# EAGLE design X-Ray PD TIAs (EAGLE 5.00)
MFG: Amp; PN: TPSB476K010R0250
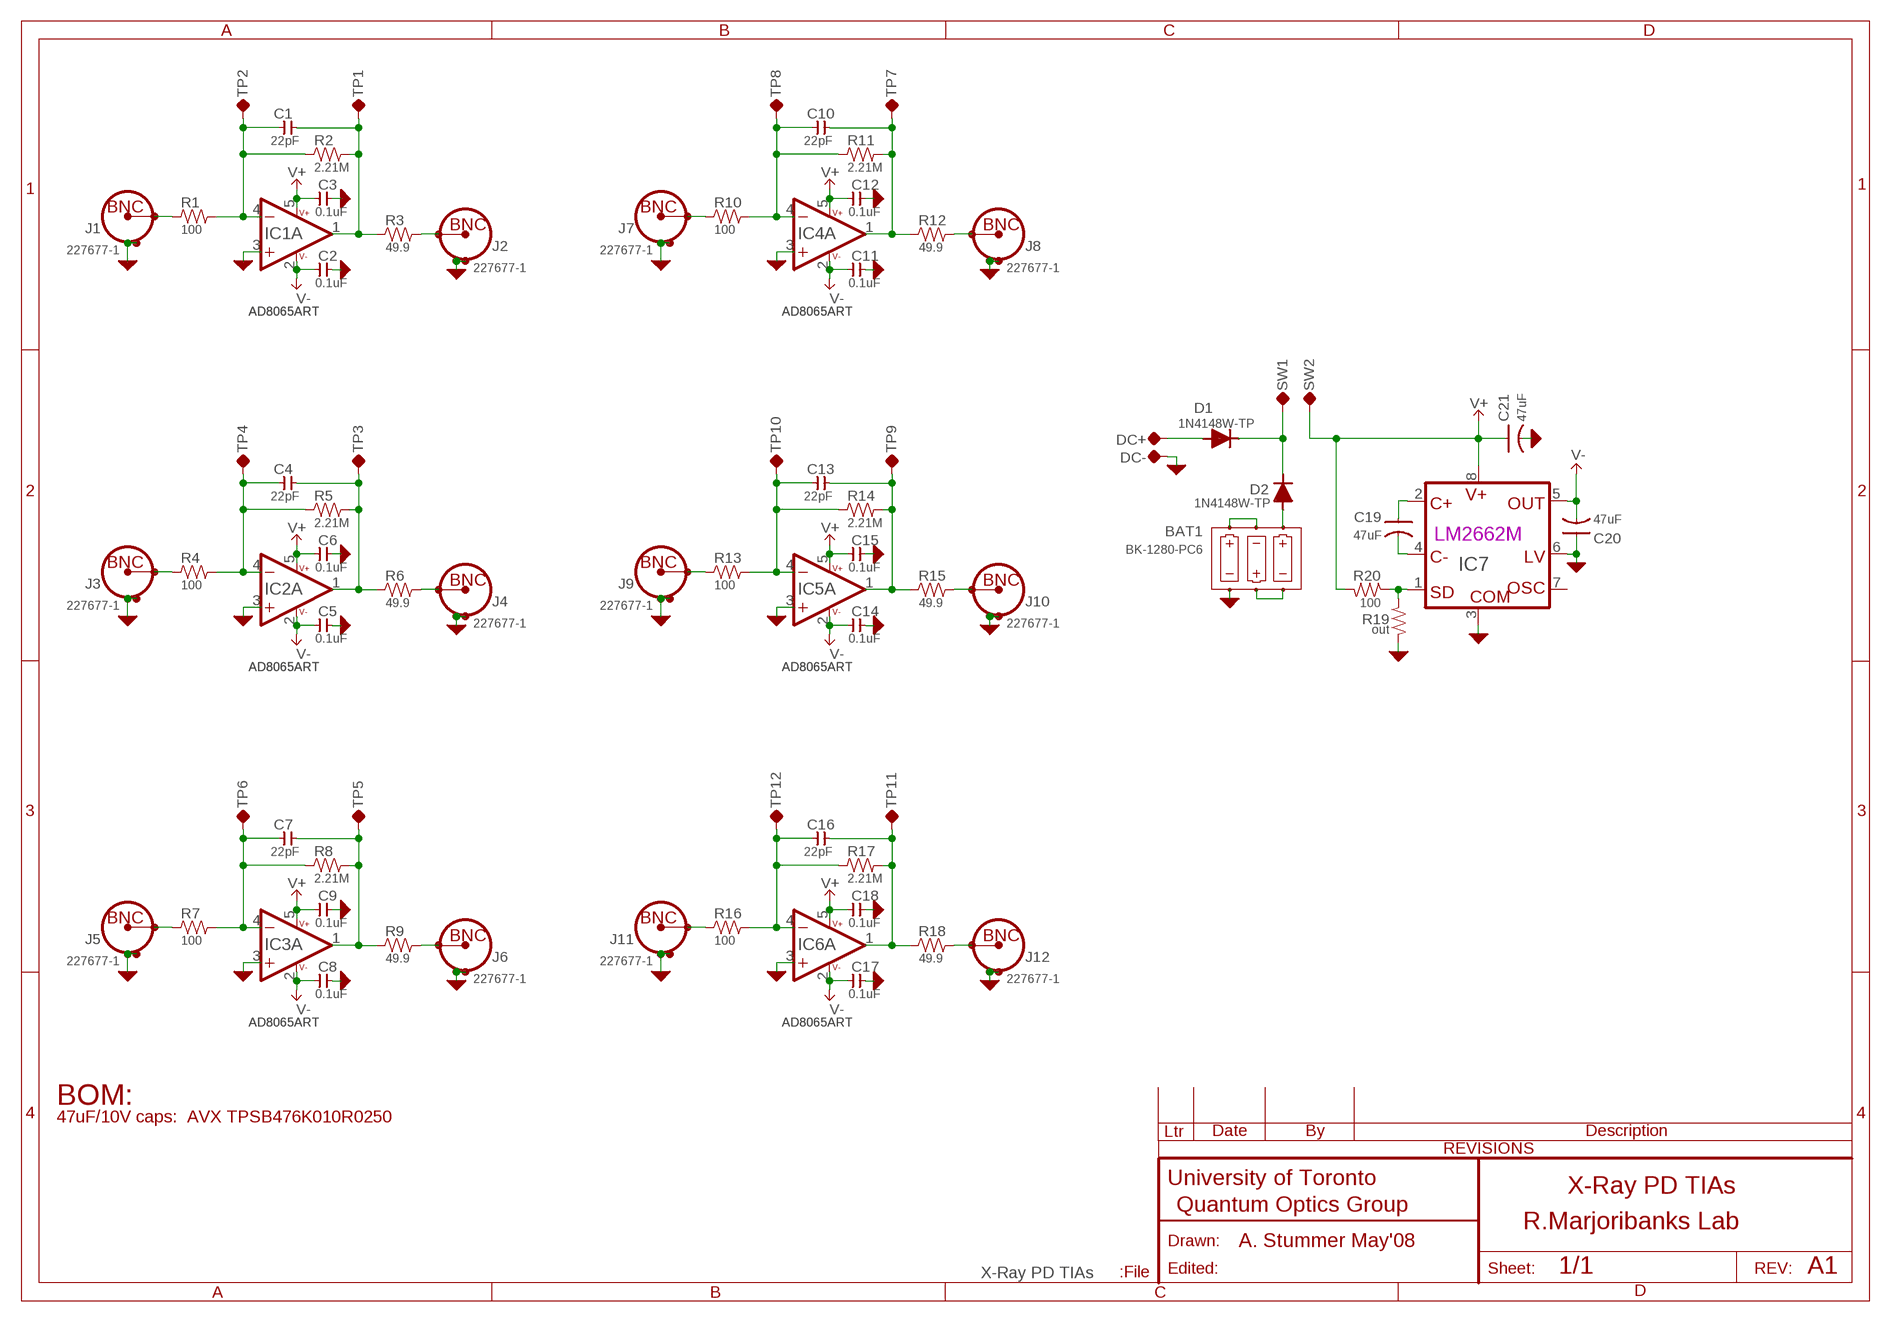
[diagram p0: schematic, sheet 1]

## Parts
BAT1  BK-1280-PC6  BATTERY-CASE-3AA-1  [BATTERY-CASE-3AA-1]
C1  22pF  CAP-H-0805  [2012(0805)]
C2  0.1uF  CAP-H-0805  [2012(0805)]
C3  0.1uF  CAP-H-0805  [2012(0805)]
C4  22pF  CAP-H-0805  [2012(0805)]
C5  0.1uF  CAP-H-0805  [2012(0805)]
C6  0.1uF  CAP-H-0805  [2012(0805)]
C7  22pF  CAP-H-0805  [2012(0805)]
C8  0.1uF  CAP-H-0805  [2012(0805)]
C9  0.1uF  CAP-H-0805  [2012(0805)]
C10  22pF  CAP-H-0805  [2012(0805)]
C11  0.1uF  CAP-H-0805  [2012(0805)]
C12  0.1uF  CAP-H-0805  [2012(0805)]
C13  22pF  CAP-H-0805  [2012(0805)]
C14  0.1uF  CAP-H-0805  [2012(0805)]
C15  0.1uF  CAP-H-0805  [2012(0805)]
C16  22pF  CAP-H-0805  [2012(0805)]
C17  0.1uF  CAP-H-0805  [2012(0805)]
C18  0.1uF  CAP-H-0805  [2012(0805)]
C19  47uF  CAP-POL-EIA-B  [EIA-B(SMB)]
C20  47uF  CAP-POL-EIA-B  [EIA-B(SMB)]
C21  47uF  CAP-POL-EIA-B  [EIA-B(SMB)]
D1  1N4148W-TP  DIODE,GENERIC-SOD123  [SOD123]
D2  1N4148W-TP  DIODE,GENERIC-SOD123  [SOD123]
DC+  TP-0.042"  [TP-0.042]
DC-  TP-0.042"  [TP-0.042]
IC1  AD8065ART  OPAMPSOT23-5  [SOT23-5]
IC2  AD8065ART  OPAMPSOT23-5  [SOT23-5]
IC3  AD8065ART  OPAMPSOT23-5  [SOT23-5]
IC4  AD8065ART  OPAMPSOT23-5  [SOT23-5]
IC5  AD8065ART  OPAMPSOT23-5  [SOT23-5]
IC6  AD8065ART  OPAMPSOT23-5  [SOT23-5]
IC7  LM2662M  LM2663M  [SOIC-8]
J1  227677-1  CONN-BNCTYPE3HORIZ  [CONN-BNC-AMP-TYPE3HORIZ]
J2  227677-1  CONN-BNCTYPE3HORIZ  [CONN-BNC-AMP-TYPE3HORIZ]
J3  227677-1  CONN-BNCTYPE3HORIZ  [CONN-BNC-AMP-TYPE3HORIZ]
J4  227677-1  CONN-BNCTYPE3HORIZ  [CONN-BNC-AMP-TYPE3HORIZ]
J5  227677-1  CONN-BNCTYPE3HORIZ  [CONN-BNC-AMP-TYPE3HORIZ]
J6  227677-1  CONN-BNCTYPE3HORIZ  [CONN-BNC-AMP-TYPE3HORIZ]
J7  227677-1  CONN-BNCTYPE3HORIZ  [CONN-BNC-AMP-TYPE3HORIZ]
J8  227677-1  CONN-BNCTYPE3HORIZ  [CONN-BNC-AMP-TYPE3HORIZ]
J9  227677-1  CONN-BNCTYPE3HORIZ  [CONN-BNC-AMP-TYPE3HORIZ]
J10  227677-1  CONN-BNCTYPE3HORIZ  [CONN-BNC-AMP-TYPE3HORIZ]
J11  227677-1  CONN-BNCTYPE3HORIZ  [CONN-BNC-AMP-TYPE3HORIZ]
J12  227677-1  CONN-BNCTYPE3HORIZ  [CONN-BNC-AMP-TYPE3HORIZ]
R1  100  R-H-0805  [2012(0805)]
R2  2.21M  R-H-0805  [2012(0805)]
R3  49.9  R-H-0805  [2012(0805)]
R4  100  R-H-0805  [2012(0805)]
R5  2.21M  R-H-0805  [2012(0805)]
R6  49.9  R-H-0805  [2012(0805)]
R7  100  R-H-0805  [2012(0805)]
R8  2.21M  R-H-0805  [2012(0805)]
R9  49.9  R-H-0805  [2012(0805)]
R10  100  R-H-0805  [2012(0805)]
R11  2.21M  R-H-0805  [2012(0805)]
R12  49.9  R-H-0805  [2012(0805)]
R13  100  R-H-0805  [2012(0805)]
R14  2.21M  R-H-0805  [2012(0805)]
R15  49.9  R-H-0805  [2012(0805)]
R16  100  R-H-0805  [2012(0805)]
R17  2.21M  R-H-0805  [2012(0805)]
R18  49.9  R-H-0805  [2012(0805)]
R19  out  R-V-0805  [2012(0805)]
R20  100  R-H-0805  [2012(0805)]
SW1  TP-0.042"  [TP-0.042]
SW2  TP-0.042"  [TP-0.042]
TP1  future use  TP-0.042"  [TP-0.042]
TP2  future use  TP-0.042"  [TP-0.042]
TP3  future use  TP-0.042"  [TP-0.042]
TP4  future use  TP-0.042"  [TP-0.042]
TP5  future use  TP-0.042"  [TP-0.042]
TP6  future use  TP-0.042"  [TP-0.042]
TP7  future use  TP-0.042"  [TP-0.042]
TP8  future use  TP-0.042"  [TP-0.042]
TP9  future use  TP-0.042"  [TP-0.042]
TP10  future use  TP-0.042"  [TP-0.042]
TP11  future use  TP-0.042"  [TP-0.042]
TP12  future use  TP-0.042"  [TP-0.042]

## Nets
AGND: BAT1.1- C2.2 C3.2 C5.2 C6.2 C8.2 C9.2 C11.2 C12.2 C14.2 C15.2 C17.2 C18.2 C20.K+(POS) C21.A-(NEG) DC-.TP IC1.3(A:+IN) IC2.3(A:+IN) IC3.3(A:+IN) IC4.3(A:+IN) IC5.3(A:+IN) IC6.3(A:+IN) IC7.3(COM) IC7.6(LV) J1.SHIELD1 J1.SHIELD2 J2.SHIELD1 J2.SHIELD2 J3.SHIELD1 J3.SHIELD2 J4.SHIELD1 J4.SHIELD2 J5.SHIELD1 J5.SHIELD2 J6.SHIELD1 J6.SHIELD2 J7.SHIELD1 J7.SHIELD2 J8.SHIELD1 J8.SHIELD2 J9.SHIELD1 J9.SHIELD2 J10.SHIELD1 J10.SHIELD2 J11.SHIELD1 J11.SHIELD2 J12.SHIELD1 J12.SHIELD2 R19.1
N$1: J1.CONDUCTOR R1.1
N$2: C1.1 IC1.4(A:-IN) R1.2 R2.1 TP2.TP
N$3: C1.2 IC1.1(A:OUT) R2.2 R3.1 TP1.TP
N$4: J2.CONDUCTOR R3.2
N$5: J3.CONDUCTOR R4.1
N$6: C4.1 IC2.4(A:-IN) R4.2 R5.1 TP4.TP
N$7: C4.2 IC2.1(A:OUT) R5.2 R6.1 TP3.TP
N$8: J4.CONDUCTOR R6.2
N$9: J5.CONDUCTOR R7.1
N$10: C7.1 IC3.4(A:-IN) R7.2 R8.1 TP6.TP
N$11: C7.2 IC3.1(A:OUT) R8.2 R9.1 TP5.TP
N$12: J6.CONDUCTOR R9.2
N$13: J7.CONDUCTOR R10.1
N$14: C10.1 IC4.4(A:-IN) R10.2 R11.1 TP8.TP
N$15: C10.2 IC4.1(A:OUT) R11.2 R12.1 TP7.TP
N$16: J8.CONDUCTOR R12.2
N$17: J9.CONDUCTOR R13.1
N$18: C13.1 IC5.4(A:-IN) R13.2 R14.1 TP10.TP
N$19: C13.2 IC5.1(A:OUT) R14.2 R15.1 TP9.TP
N$20: J10.CONDUCTOR R15.2
N$21: J11.CONDUCTOR R16.1
N$22: C16.1 IC6.4(A:-IN) R16.2 R17.1 TP12.TP
N$23: C16.2 IC6.1(A:OUT) R17.2 R18.1 TP11.TP
N$24: J12.CONDUCTOR R18.2
N$25: C19.K+(POS) IC7.2(C+)
N$26: C19.A-(NEG) IC7.4(C-)
N$27: BAT1.1+ BAT1.2-
N$28: BAT1.2+ BAT1.3-
N$29: BAT1.3+ D2.A
N$30: D1.C D2.C SW1.TP
N$31: D1.A DC+.TP
N$32: IC7.1(SD) R19.2 R20.1
V+: C3.1 C6.1 C9.1 C12.1 C15.1 C18.1 C21.K+(POS) IC1.5(B:V+) IC2.5(B:V+) IC3.5(B:V+) IC4.5(B:V+) IC5.5(B:V+) IC6.5(B:V+) IC7.8(V+) R20.2 SW2.TP
V-: C2.1 C5.1 C8.1 C11.1 C14.1 C17.1 C20.A-(NEG) IC1.2(B:V-) IC2.2(B:V-) IC3.2(B:V-) IC4.2(B:V-) IC5.2(B:V-) IC6.2(B:V-) IC7.5(OUT)
Unconnected: IC7.7(OSC)

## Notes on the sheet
- BOM:
- 47uF/10V caps:  AVX TPSB476K010R0250
- X-Ray PD TIAs
- R.Marjoribanks Lab
- A. Stummer May'08
- A1

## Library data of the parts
BAT1 = QuantumOptics:BATTERY-CASE-3AA-1: Battery holder, 3 AA, Memory Protection Devices Inc, BK-1280-PC6
C1-C18 = QuantumOptics:CAP-H-: Cap, SMT and Through-hole, 0402 and up.
C19-C21 = QuantumOptics:CAP-POL-: Capacitor, Polarized, SMT 0805 and up, probably tantalum.
D1 D2 = QuantumOptics:DIODE,GENERIC: Diode, Generic, plain old vanilla diodes.
DC+ DC- SW1 SW2 TP1-TP12 = QuantumOptics:TP: Testpoint, test point on schematic, on PCB either SMT pad, small hole or loop style TP.
IC1-IC6 = QuantumOptics:OPAMP: Op Amp, generic, pick the right package. e.g. AD8605: SOT-23-5, RRIO, 10MHz, Ib = 1pA, Vio < 65uV, 2.7-5.5V.
IC7 = QuantumOptics:LM2663: LM2663, switched cap DC-DC converter. Inverter, doubler, supply splitter.
J1-J12 = QuantumOptics:CONN-BNC: BNC PCB, horizontal, Amp 227677-1, nut 1-329631-2, shoulder washer 330620. The two shield connections allow the assembly on either side of the board. http://catalog.tycoelectronics.com/TE/bin/TE.Connect?C=1&PN=227677-1&M=STARTSWITH&LG=1&I=13&button.x=0&button.y=0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
R1-R18 R20 = QuantumOptics:R-H-*: Resistor, SMT & Through-Hole, horizontal symbol
R19 = QuantumOptics:R-V-*: Resistor, SMT & Through-Hole, vertical symbol

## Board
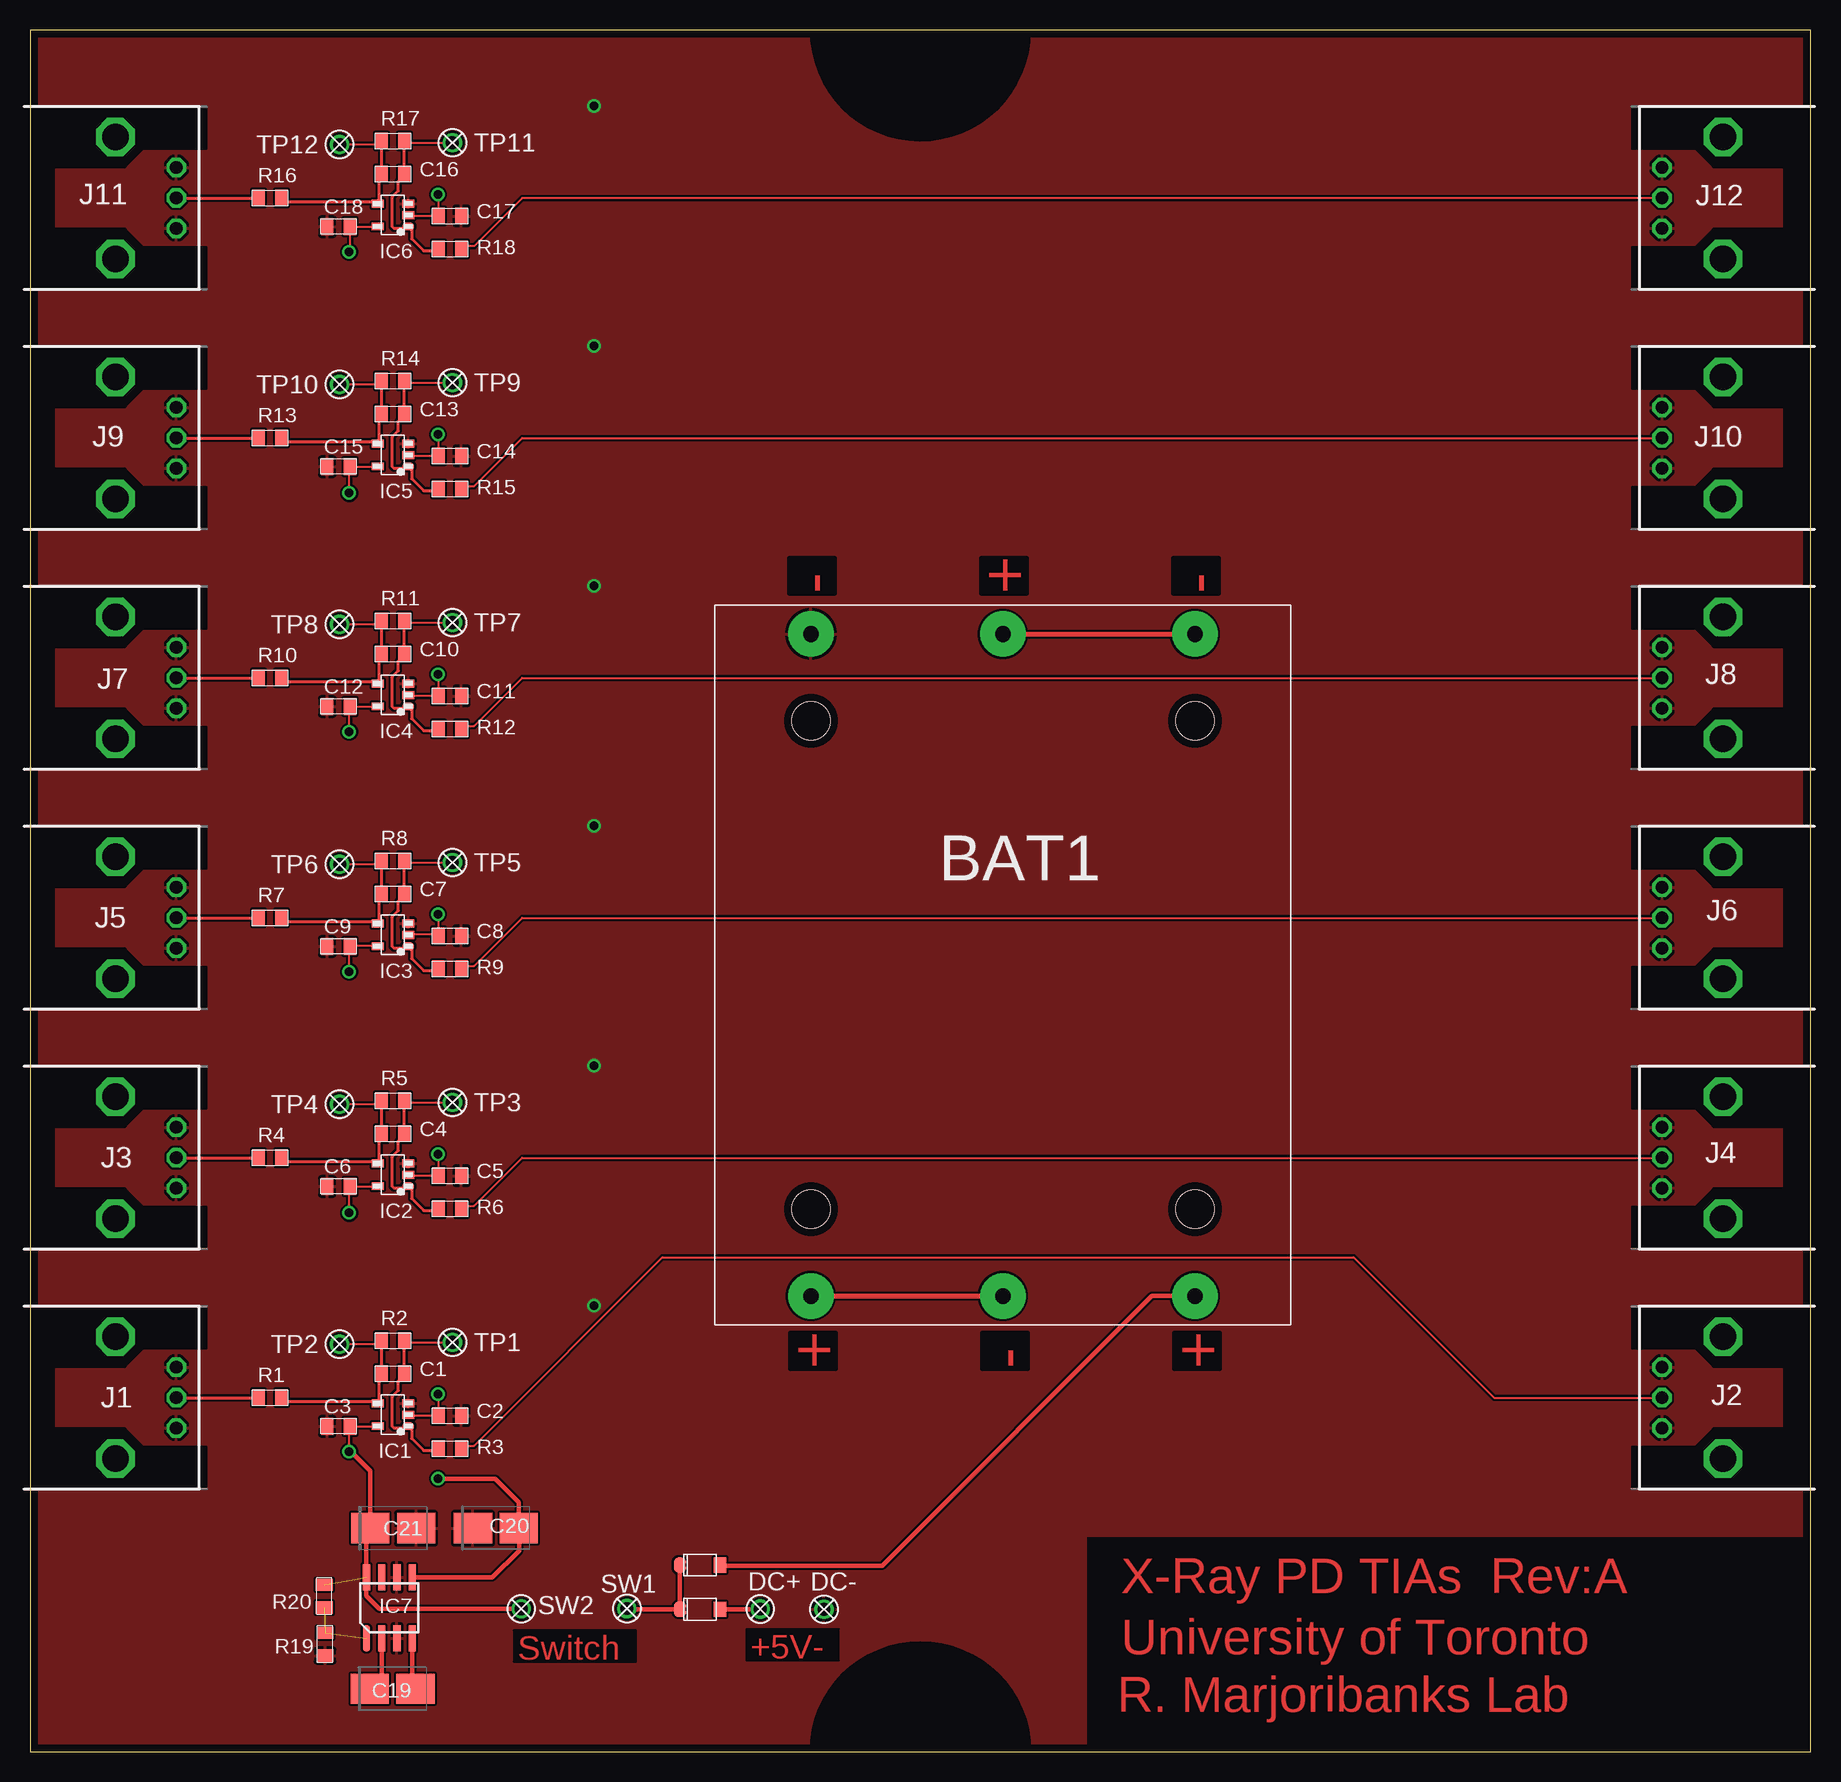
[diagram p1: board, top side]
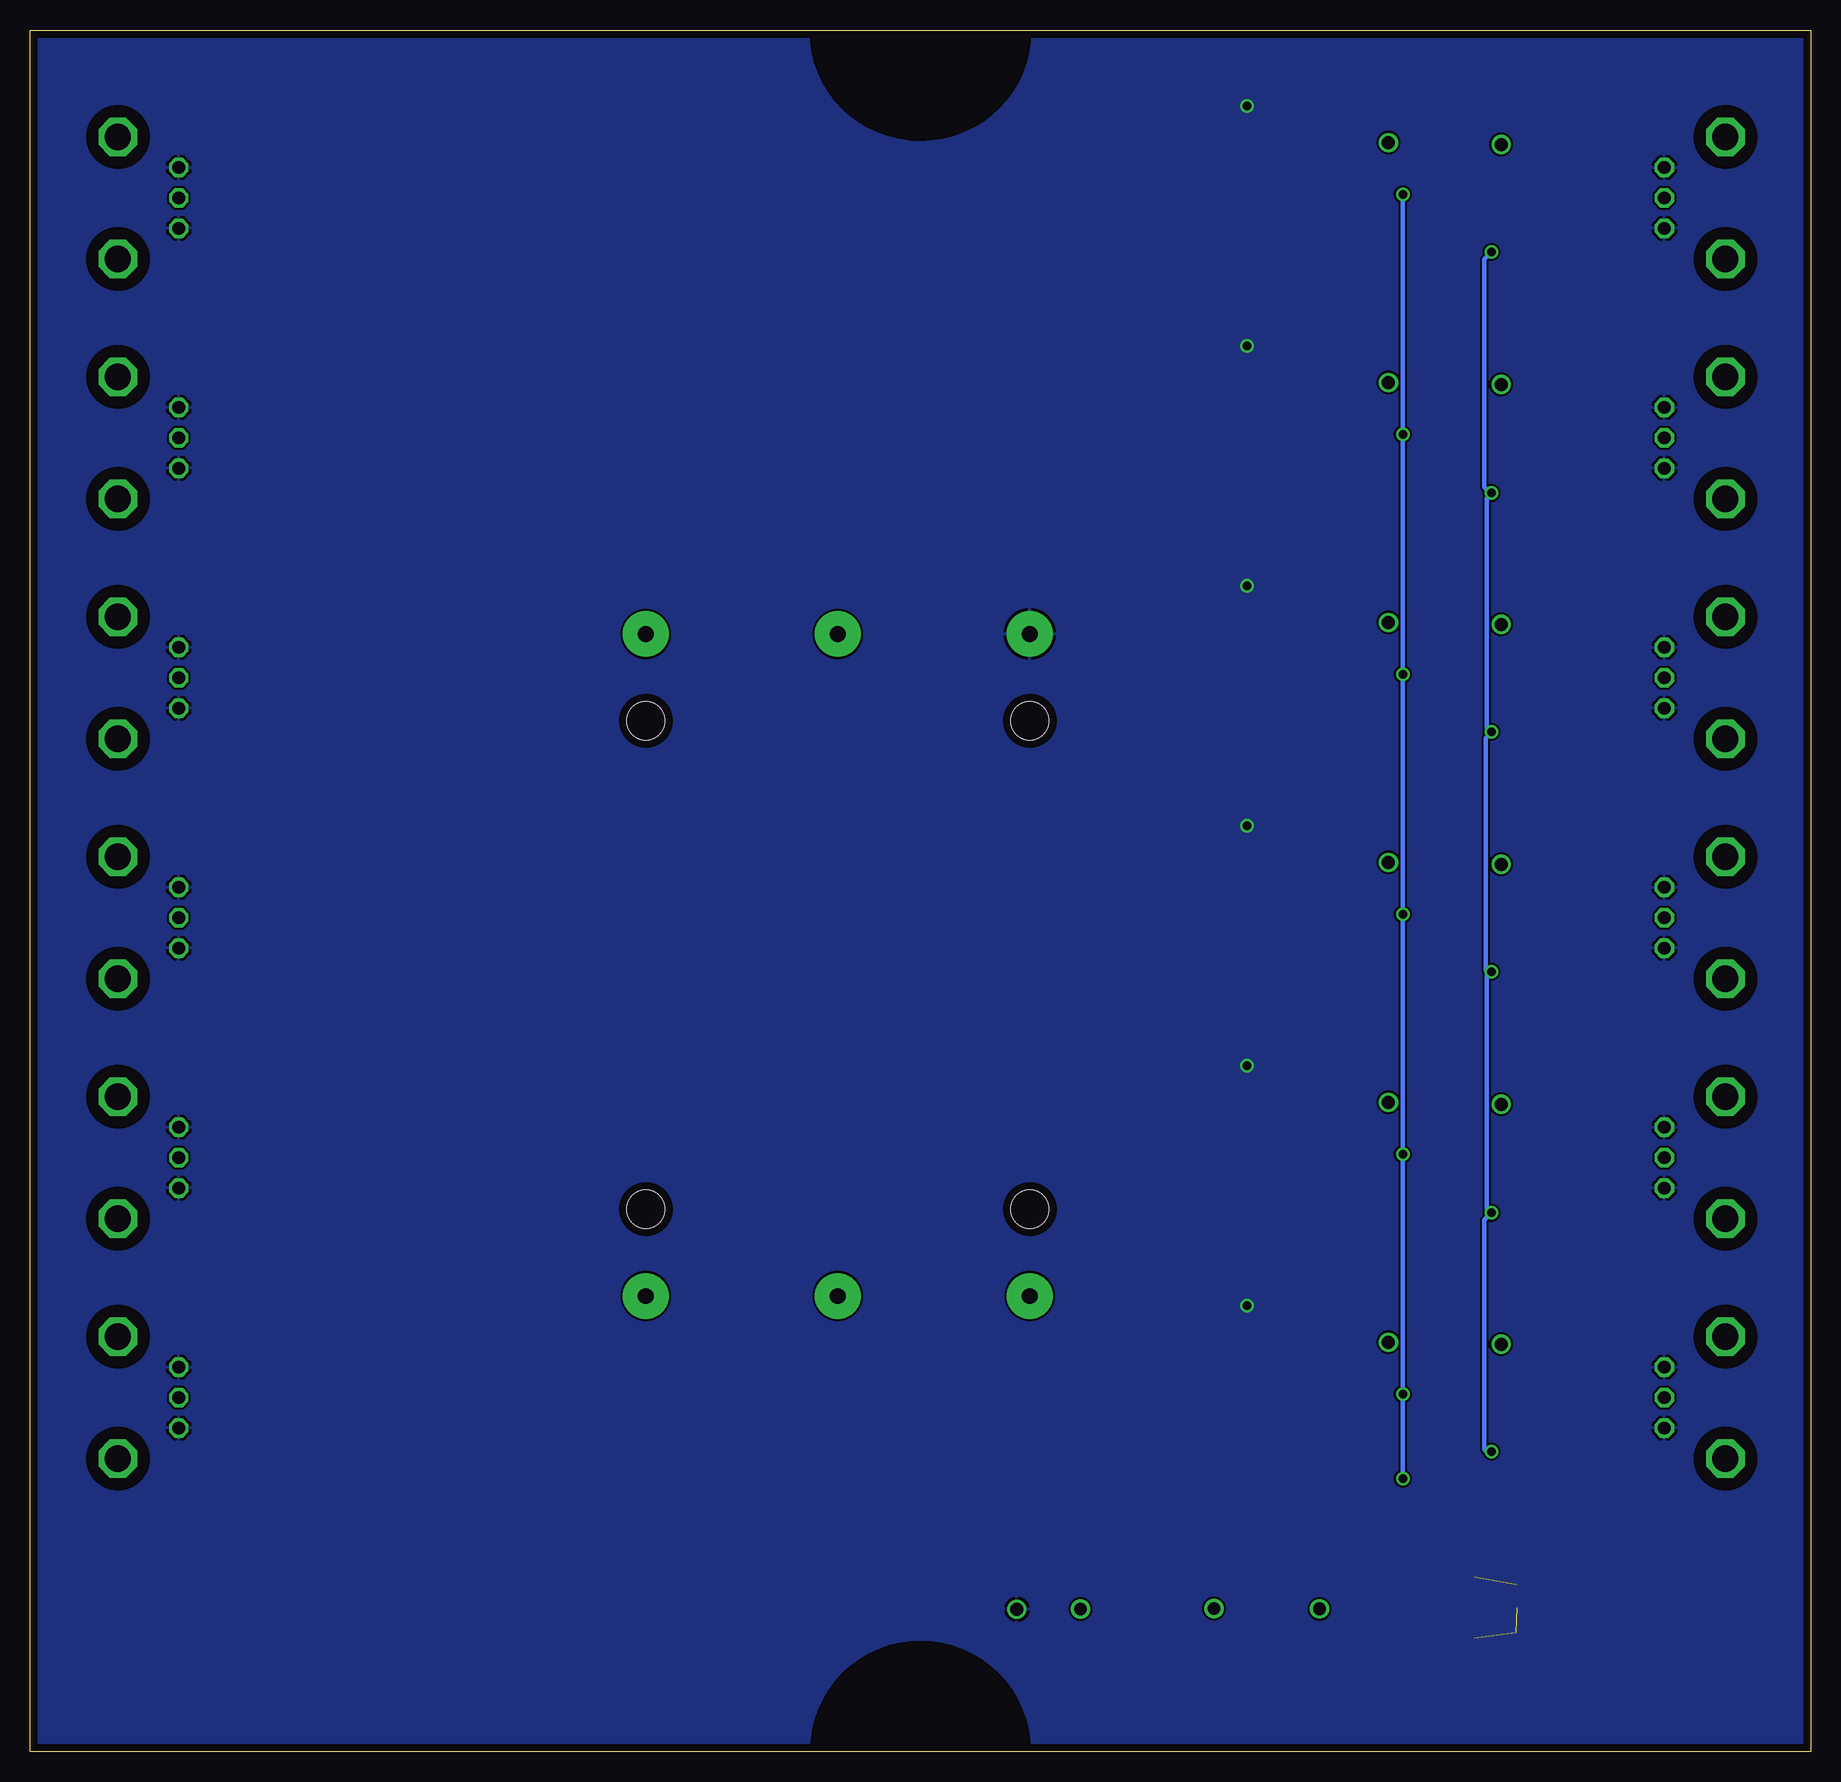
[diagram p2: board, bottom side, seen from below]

Size 148.4 x 143.5 mm. Coordinates in mm from the lower left corner, seen from the top.
Outline: 0,0 148.4,0 148.4,143.5 0,143.5 0,0
Copper layers (1*16): Top 0.035mm / dielectric 1.5mm / Bottom 0.035mm
Design rules "DRC standard check (7mil trace and gap, 20mil drill, etc)": minimum track width 7mil, minimum drill 20mil, track to track 7mil, track to pad 7mil, pad to pad 7mil, via to via 7mil, smd to smd 7mil, copper to edge 25mil, drill to drill 8mil, minimum pad ring 10mil, minimum via ring 8mil, stop-mask expansion 4mil, vias tented up to drill 0mil, thermal gap 10mil
tRestrict: 10 lines
bRestrict: 2 lines

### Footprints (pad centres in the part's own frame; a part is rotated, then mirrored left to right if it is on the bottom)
BATTERY-CASE-3AA-1 = drill 1.321 pad 3.81 round: 1+ -27.6,16; 1- 27.6,16; 2+ 27.6,0; 2- -27.6,0; 3+ -27.6,-16; 3- 27.6,-16 | hole 3.175: -20.35,16; -20.35,-16; 20.35,-16; 20.35,16
2012(0805) = smd 1.016 x 1.397: 1 -0.953,0; 2 0.953,0
EIA-B(SMB) = smd 3.175 x 2.54: A- -1.905,0; K+ 1.905,0
SOD123 = smd 1.016 x 1.27: A 1.676,0; C -1.676,0
TP-0.042 = drill 1.067 round: TP 0,0
SOT23-5 = smd 0.635 x 0.991: 1 -0.635,-1.27; 2 0.318,-1.27; 3 1.27,-1.27; 4 1.27,1.27; 5 -0.635,1.27
SOIC-8 = smd 0.6 x 2.2: 1 -1.27,-2.54; 2 0,-2.54; 3 1.27,-2.54; 4 2.54,-2.54; 5 2.54,2.54; 6 1.27,2.54; 7 0,2.54; 8 -1.27,2.54
CONN-BNC-AMP-TYPE3HORIZ = drill 1.067 octagon: CONDUCTOR 0,-12.7; SHIELD1 -2.54,-12.7; SHIELD2 2.54,-12.7 | drill 2.184 octagon: P$1 -5.08,-7.62; P$2 5.08,-7.62

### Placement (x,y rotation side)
BAT1  81.08,65.56 90 top
C1  30.25,31.5 0 top
C2  35,28 0 top
C3  25.72,27.11 180 top
C4  30.25,51.5 0 top
C5  35,48 0 top
C6  25.72,47.11 180 top
C7  30.25,71.5 0 top
C8  35,68 0 top
C9  25.72,67.11 180 top
C10  30.25,91.5 0 top
C11  35,88 0 top
C12  25.72,87.11 180 top
C13  30.25,111.5 0 top
C14  35,108 0 top
C15  25.72,107.11 180 top
C16  30.25,131.5 0 top
C17  35,128 0 top
C18  25.72,127.11 180 top
C19  30.22,5.23 180 top
C20  38.82,18.62 180 top
C21  30.27,18.61 180 top
D1  55.83,11.85 0 top
D2  55.83,15.54 0 top
DC+  60.86,11.87 0 top
DC-  66.16,11.86 0 top
IC1  30.25,27.75 90 top
IC2  30.25,47.75 90 top
IC3  30.25,67.75 90 top
IC4  30.25,87.75 90 top
IC5  30.25,107.75 90 top
IC6  30.25,127.75 90 top
IC7  29.31,11.98 0 top
J1  -0.5,29.5 90 top
J2  148.7,29.5 270 top
J3  -0.5,49.5 90 top
J4  148.7,49.5 270 top
J5  -0.5,69.5 90 top
J6  148.7,69.5 270 top
J7  -0.5,89.5 90 top
J8  148.7,89.5 270 top
J9  -0.5,109.5 90 top
J10  148.7,109.5 270 top
J11  -0.5,129.5 90 top
J12  148.7,129.5 270 top
R1  20,29.5 0 top
R2  30.25,34.25 0 top
R3  35,25.25 0 top
R4  20,49.5 0 top
R5  30.25,54.25 0 top
R6  35,45.25 0 top
R7  20,69.5 0 top
R8  30.25,74.25 0 top
R9  35,65.25 0 top
R10  20,89.5 0 top
R11  30.25,94.25 0 top
R12  35,85.25 0 top
R13  20,109.5 0 top
R14  30.25,114.25 0 top
R15  35,105.25 0 top
R16  20,129.5 0 top
R17  30.25,134.25 0 top
R18  35,125.25 0 top
R19  24.59,8.95 90 top
R20  24.51,12.95 90 top
SW1  49.74,11.92 180 top
SW2  40.94,11.89 0 top
TP1  35.2,34.11 0 top
TP2  25.8,33.95 180 top
TP3  35.2,54.11 0 top
TP4  25.8,53.95 180 top
TP5  35.2,74.11 0 top
TP6  25.8,73.95 180 top
TP7  35.2,94.11 0 top
TP8  25.8,93.95 180 top
TP9  35.2,114.11 0 top
TP10  25.8,113.95 180 top
TP11  35.2,134.11 0 top
TP12  25.8,133.95 180 top
U$36  [TITLEBLOCK_PCB]  0,-2.54 0 top

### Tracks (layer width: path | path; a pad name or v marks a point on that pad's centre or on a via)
AGND  (via drill 0.71)
  other vias: 46.99,137.16 46.99,117.16 46.99,97.16 46.99,77.16 46.99,57.16 46.99,37.16
  pour Top: 0,0 88,0 88,18 148.4,18 148.4,143.5 0,143.5
  pour Bottom: 0,0 148.4,0 148.4,143.5 0,143.5
N$1
  Top 0.254: J1.CONDUCTOR R1.1
N$2
  Top 0.18: R2.1 29.35,34.25 29.05,33.95 TP2.TP
  Top 0.254: R1.2 21.4,29.2 28.5,29.2 IC1.4 29.1,29.3 29.1,30.9 C1.1 29.3,32.1 29.3,33.6 R2.1
N$3
  Top 0.18: R2.2 31.25,34.25 31.39,34.11 TP1.TP
  Top 0.254: R2.2 31.2,33.6 31.2,32.1 C1.2 30.7,30.9 30.7,30.1 30.2,29.6 30.2,27.1 30.3,27 31.1,27 IC1.1 31.8,26.8 31.8,26.1 32.8,25.1 33.6,25.1 R3.1
N$4
  Top 0.18: R3.2 35.95,25.5 37,25.5 52.7,41.2 110.3,41.2 122,29.5 J2.CONDUCTOR
N$5
  Top 0.254: J3.CONDUCTOR R4.1
N$6
  Top 0.18: R5.1 29.2,54.25 28.9,53.95 TP4.TP
  Top 0.254: R4.2 21.4,49.2 28.5,49.2 IC2.4 29.1,49.3 29.1,50.9 C4.1 29.3,52.1 29.3,53.6 R5.1
N$7
  Top 0.18: R5.2 31.34,54.11 TP3.TP
  Top 0.254: R5.2 31.2,53.6 31.2,52.1 C4.2 30.7,50.9 30.7,50.1 30.2,49.6 30.2,47.1 30.3,47 31.1,47 IC2.1 31.8,46.8 31.8,46.1 32.8,45.1 33.6,45.1 R6.1
N$8
  Top 0.18: J4.CONDUCTOR 41,49.5 37,45.5 35.95,45.5 R6.2
N$9
  Top 0.254: J5.CONDUCTOR R7.1
N$10
  Top 0.18: R8.1 29.25,74.25 28.95,73.95 TP6.TP
  Top 0.254: R7.2 21.4,69.2 28.5,69.2 IC3.4 29.1,69.3 29.1,70.9 C7.1 29.3,72.1 29.3,73.6 R8.1
N$11
  Top 0.18: R8.2 31.34,74.11 TP5.TP
  Top 0.254: R8.2 31.2,73.6 31.2,72.1 C7.2 30.7,70.9 30.7,70.1 30.2,69.6 30.2,67.1 30.3,67 31.1,67 IC3.1 31.8,66.8 31.8,66.1 32.8,65.1 33.6,65.1 R9.1
N$12
  Top 0.18: J6.CONDUCTOR 41,69.5 37,65.5 35.95,65.5 R9.2
N$13
  Top 0.254: J7.CONDUCTOR R10.1
N$14
  Top 0.18: R11.1 29.2,94.25 28.9,93.95 TP8.TP
  Top 0.254: R10.2 21.4,89.2 28.5,89.2 IC4.4 29.1,89.3 29.1,90.9 C10.1 29.3,92.1 29.3,93.6 R11.1
N$15
  Top 0.18: R11.2 31.34,94.11 TP7.TP
  Top 0.254: R11.2 31.2,93.6 31.2,92.1 C10.2 30.7,90.9 30.7,90.1 30.2,89.6 30.2,87.1 30.3,87 31.1,87 IC4.1 31.8,86.8 31.8,86.1 32.8,85.1 33.6,85.1 R12.1
N$16
  Top 0.18: J8.CONDUCTOR 41,89.5 37,85.5 36.5,85.5 36,85 35.95,85 R12.2
N$17
  Top 0.254: J9.CONDUCTOR R13.1
N$18
  Top 0.18: R14.1 29,113.95 TP10.TP
  Top 0.254: R13.2 21.4,109.2 28.5,109.2 IC5.4 29.1,109.3 29.1,110.9 C13.1 29.3,112.1 29.3,113.6 R14.1
N$19
  Top 0.18: R14.2 31.34,114.11 TP9.TP
  Top 0.254: R14.2 31.2,113.6 31.2,112.1 C13.2 30.7,110.9 30.7,110.1 30.2,109.6 30.2,107.1 30.3,107 31.1,107 IC5.1 31.8,106.8 31.8,106.1 32.8,105.1 33.6,105.1 R15.1
N$20
  Top 0.18: J10.CONDUCTOR 41,109.5 37,105.5 36.5,105.5 36,105 35.95,105 R15.2
N$21
  Top 0.254: J11.CONDUCTOR R16.1
N$22
  Top 0.18: R17.1 29,133.95 TP12.TP
  Top 0.254: R16.2 21.4,129.2 28.5,129.2 IC6.4 29.1,129.3 29.1,130.9 C16.1 29.3,132.1 29.3,133.6 R17.1
N$23
  Top 0.18: R17.2 31.34,134.11 TP11.TP
  Top 0.254: R17.2 31.2,133.6 31.2,132.1 C16.2 30.7,130.9 30.7,130.1 30.2,129.6 30.2,127.1 30.3,127 31.1,127 IC6.1 31.8,126.8 31.8,126.1 32.8,125.1 33.6,125.1 R18.1
N$24
  Top 0.18: J12.CONDUCTOR 41,129.5 37,125.5 36.5,125.5 36,125 35.95,125 R18.2
N$25
  Top 0.36: C19.K+ 28.25,5.23 28.25,5.25 29.31,6.31 IC7.2
N$26
  Top 0.36: C19.A- 32.25,5.23 32.25,5.25 31.85,5.65 IC7.4
N$27
  Top 0.406: 81.1,37.96 BAT1.2- | BAT1.1+ 81.1,37.96 | 81.1,37.96 81.1,37.9
N$28
  Top 0.406: 97.1,93.16 BAT1.3- | BAT1.2+ 97.1,93.16 | 97.1,93.16 97.1,93.1
N$29
  Top 0.36: BAT1.3+ 93.46,37.96 71,15.5 57.51,15.5 | 57.51,15.5 57.5,15.5 | D2.A 57.51,15.5
N$30
  Top 0.36: D1.C 54.15,11.75 54.25,11.75 D1.C | D1.C D2.C | SW1.TP 49.74,12 49.75,12 49.9,11.85 D1.C
N$31
  Top 0.36: D1.A 57.51,12 57.5,12 57.63,11.87 DC+.TP
N$32  (2 unrouted)
V+  (via drill 0.71)  (1 unrouted)
  Top 0.18: v26.6,25 26.6,27.04 C3.1 26.7,27.1 28.96,27.1 IC1.5 | v26.6,65 26.6,67.04 C9.1 26.7,67.1 26.7,67.2 28.89,67.2 IC3.5 | IC2.5 28.96,47.1 26.7,47.1 C6.1 26.6,47.04 26.6,45 26.7,44.9 v26.6,44.9 | IC4.5 28.96,87.1 26.7,87.1 C12.1 26.6,87.04 v26.6,85 | IC5.5 28.96,107.1 26.7,107.1 C15.1 26.6,107.04 v26.6,104.9 | 26.7,127.1 26.7,127.2 | 26.7,127.1 C18.1 26.68,127.1 29,127.1 IC6.5 | v26.6,125 26.7,125.1 26.7,127.1
  Top 0.36: SW2.TP 29.11,11.89 28,13 28,14.52 IC7.8 28.04,18.04 28.5,18.5 28.5,18.61 C21.K+ 28.36,23.39 26.75,25 v26.6,25
  Bottom 0.18: 27,65 27.1,65.1 | 26.8,105 26.7,105 v26.6,104.9 | 26.7,45.1 26.7,45 v26.6,44.9
  Bottom 0.36: v26.6,44.9 27.2,44.3 27.2,25.2 27,25 v26.6,25 | v26.6,125 27.2,124.4 27.2,105.4 26.8,105 | v26.6,104.9 27,104.5 27,85.2 26.8,85.2 v26.6,85 27.1,84.5 27.1,65.1 | v26.6,65 27,65 27,45.1 26.7,45.1
V-  (via drill 0.71)
  Top 0.18: v34,29.8 34,28.05 C2.1 31.59,28 IC1.2 | C5.1 34,48.05 v34,49.8 | v34,69.8 34,68 C8.1 33.95,68.1 31.5,68.1 IC3.2 | C5.1 34.1,48 | C5.1 34,48 | IC2.2 31.59,48 C5.1 | C11.1 34.1,88 | C11.1 34,88 | IC4.2 31.59,88 C11.1 | 34,89.9 v34,89.8 34,88.05 C11.1 | C14.1 34.1,108 | C14.1 34,108 | IC5.2 31.59,108 C14.1 | C14.1 34,108.05 v34,109.8 | IC6.2 31.59,128 C17.1 34,128.05 v34,129.8 34,129.9
  Top 0.36: IC7.5 38.52,14.52 40.75,16.75 40.75,18.75 40.73,18.75 C20.A- 40.73,20.77 38.75,22.75 v34,22.75
  Bottom 0.18: 34,89.9 v34,89.8
  Bottom 0.36: v34,129.8 v34,109.8 34,89.9 v34,69.8 v34,49.8 v34,29.8 v34,22.75

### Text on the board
Top: X-Ray PD TIAs Rev:A | Switch | +5V- | University of Toronto | R. Marjoribanks Lab
Document: Cabinet: Hammond 1598E | X-Ray PD TIAs | R. Marjoribanks Lab | A. Stummer May 2008 | A1 | 0.18mm | 0.36mm | 0.18mm | 0.25mm | 0.1mm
